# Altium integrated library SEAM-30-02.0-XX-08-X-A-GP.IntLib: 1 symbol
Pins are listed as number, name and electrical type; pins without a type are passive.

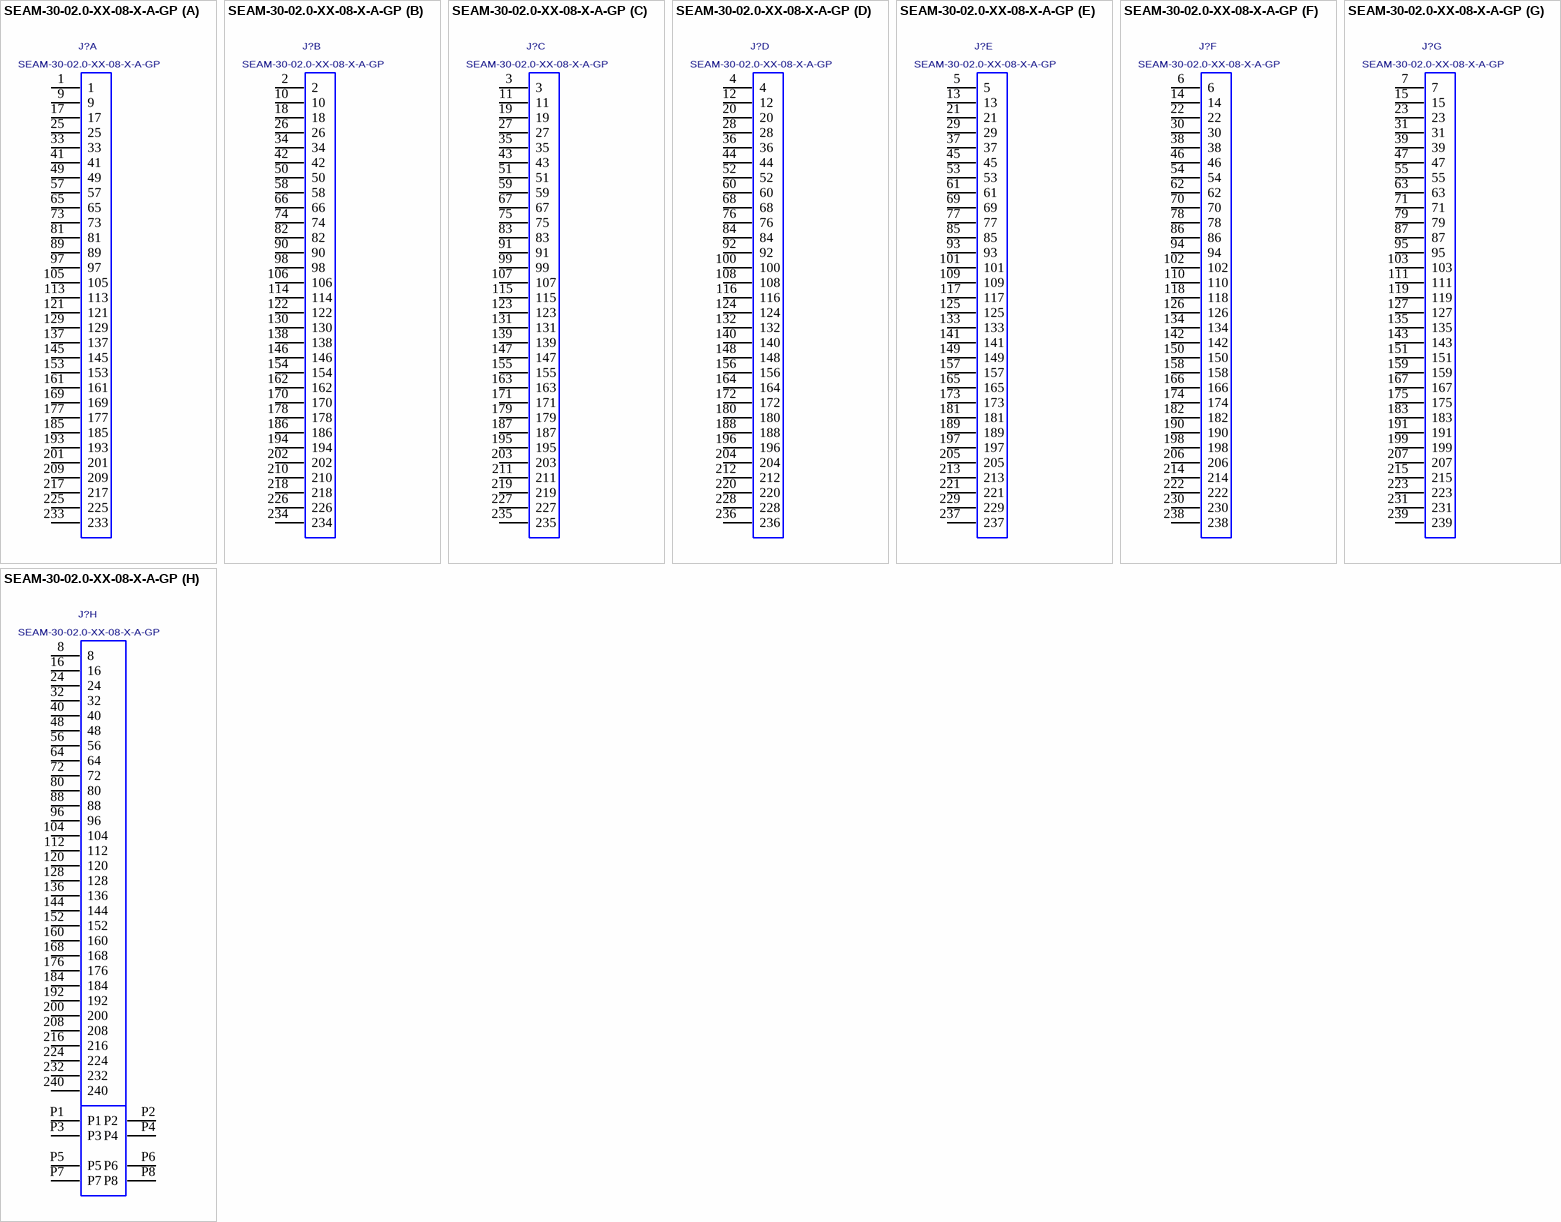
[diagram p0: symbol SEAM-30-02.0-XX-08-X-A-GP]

## SEAM-30-02.0-XX-08-X-A-GP
designator J?
0.050" TERMINAL ARRAY ASSEMBLY.; MANUFACTURER: SAMTEC
footprint SEAM-30-02.0-XX-08-X-A-GP
part A pins: 1, 9, 17, 25, 33, 41, 49, 57, 65, 73, 81, 89, 97, 105, 113, 121, 129, 137, 145, 153, 161, 169, 177, 185, 193, 201, 209, 217, 225, 233
part B pins: 2, 10, 18, 26, 34, 42, 50, 58, 66, 74, 82, 90, 98, 106, 114, 122, 130, 138, 146, 154, 162, 170, 178, 186, 194, 202, 210, 218, 226, 234
part C pins: 3, 11, 19, 27, 35, 43, 51, 59, 67, 75, 83, 91, 99, 107, 115, 123, 131, 139, 147, 155, 163, 171, 179, 187, 195, 203, 211, 219, 227, 235
part D pins: 4, 12, 20, 28, 36, 44, 52, 60, 68, 76, 84, 92, 100, 108, 116, 124, 132, 140, 148, 156, 164, 172, 180, 188, 196, 204, 212, 220, 228, 236
part E pins: 5, 13, 21, 29, 37, 45, 53, 61, 69, 77, 85, 93, 101, 109, 117, 125, 133, 141, 149, 157, 165, 173, 181, 189, 197, 205, 213, 221, 229, 237
part F pins: 6, 14, 22, 30, 38, 46, 54, 62, 70, 78, 86, 94, 102, 110, 118, 126, 134, 142, 150, 158, 166, 174, 182, 190, 198, 206, 214, 222, 230, 238
part G pins: 7, 15, 23, 31, 39, 47, 55, 63, 71, 79, 87, 95, 103, 111, 119, 127, 135, 143, 151, 159, 167, 175, 183, 191, 199, 207, 215, 223, 231, 239
part H pins: 8, 16, 24, 32, 40, 48, 56, 64, 72, 80, 88, 96, 104, 112, 120, 128, 136, 144, 152, 160, 168, 176, 184, 192, 200, 208, 216, 224, 232, 240, P1, P2, P3, P4, P5, P6, P7, P8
